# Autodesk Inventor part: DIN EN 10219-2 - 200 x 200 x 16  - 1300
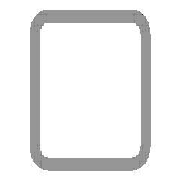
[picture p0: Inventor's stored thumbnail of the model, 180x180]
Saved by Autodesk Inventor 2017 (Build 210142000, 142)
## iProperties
Created: 2017-11
Part Number: DIN EN 10219-2 - 200 x 200 x 16  - 1300
Material: Steel, Mild
Description: Cold formed welded structural hollow sections of non-alloy and fine grain structural steel
Document SubType Name: Modeling
Standard: DIN
Designer: iusti
Standard Revision: 2006-07
Standards Organization: DIN
Language: en-US
Size Designation: 200 x 200 x 16
Categories: <MemberInstance><Categories><Category DisplayName="Structural Shapes" InternalName="089c4875-fa83-4c05-b084-43b9cc11f5ed" Mnemonic="GRDR"><CategoryParameter Dis
Stock Number: 200 x 200 x 16
Mass: 108961 g
Surface Area: 17564.1 cm^2
Volume: 13880.4 cm^3
Density: 7.85 g/cm^3
Appearance: Semi-Polished
_CCFamilyMember: 103
_CCFamilyDisplayName: DIN EN 10219-2 (Square Hollow Section - Cold Formed) - Cold formed welded structural hollow sections of non-alloy and fine grain structural steel
_FrameMemberDoc: Frame Member File
_Version: 15.0.0
_GetPNFromCC: 1
G_L: 1300.000 mm
G_W: 200.000 mm
G_H: 200.000 mm
+1055AC61-50C7-4DA5-AE5C-F84627A246C8+CUTDETAIL1: Cut
+221E46B8-E6FF-404F-B431-F4B8D67D182E+CUTDETAIL2: Cut
IsCustomPart: 1
Author: iusti
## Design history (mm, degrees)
node "Start plane"
node "End plane"
sketch "Sketch"
  geometry: L1 (-100, -52)-(-100, 52); L2 (-52, 100)-(52, 100); L3 (100, 52)-(100, -52); L4 (52, -100)-(-52, -100); L5 (-52, 84)-(52, 84); L6 (84, 52)-(84, -52); L7 (52, -84)-(-52, -84); L8 (-84, -52)-(-84, 52); L9 (0, 153.918)-(0, -153.918) reference; L10 (-153.918, 0)-(153.918, 0) reference; A1 r 48 centre (-52, -52) between (-100, -52) and (-52, -100); A2 r 48 centre (-52, 52) between (-52, 100) and (-100, 52); A3 r 48 centre (52, 52) between (100, 52) and (52, 100); A4 r 48 centre (52, -52) between (52, -100) and (100, -52); A5 r 32 centre (-52, 52) between (-52, 84) and (-84, 52); A6 r 32 centre (52, 52) between (84, 52) and (52, 84); A7 r 32 centre (52, -52) between (52, -84) and (84, -52); A8 r 32 centre (-52, -52) between (-84, -52) and (-52, -84)
  constraints: 16 end point, 16 point on circle, 8 centre point, 8 tangent, 4 parallel, 3 equal radius, 2 perpendicular, 7 other
  dimensions: "d7" = 48 radius of A1 (= G_IR); "d10" = 200 distance between parallel lines of L2 L4 (= G_H); "d11" = 200 distance between parallel lines of L1 L3 (= G_W); "d12" = 16 distance between parallel lines of L3 L6 (= G_T); "d15" = 100 distance between parallel lines of L2 L10 (= 0.5 x d10); "d16" = 100 distance between parallel lines of L9 L3 (= 0.5 x d11)
extrude "Body" new body sketch "Sketch" stored distance "d3" = 1300 (= G_L); taper "d4" = 0 deg
node "Driven Length"
  sketch "Sketch3"
    geometry: L1 (0, 0)-(10, 0) reference
    constraints: 2 end point, 1 horizontal
  workplane "Work Plane3"
  sketch "Sketch4"
    geometry: L1 (-2, 100)-(12, 100) reference; L2 (-2, 1400)-(12, 1400) reference
    dimensions: "d18" = 1300 distance between parallel lines of L1 L2 (derived)
workplane "Work Plane4"
split "Split1"
workplane "Work Plane5"
split "Split2"
body "Solid1"
other parameters: "G_W" = 200 [user parameter; used in 1 equation term], "G_H" = 200 [user parameter; used in 1 equation term], "G_T" = 16 [user parameter; used in 1 equation term], "G_IR" = 48 [user parameter; used in 1 equation term], "G_L" = 1300 (= d18) [user parameter; used in 1 equation term], "d17" = 90 deg
